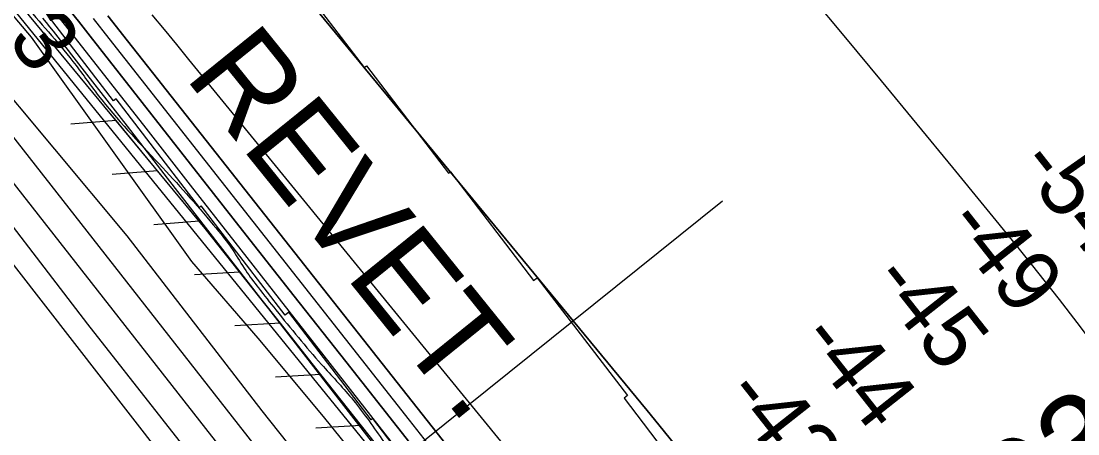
# Model space of a CAD drawing. Extents: x 3887375 to 3925618, y 296674 to 322633.
# Drawn here: x 3898902 to 3900036, y 305455 to 305898 of the extents above; entities that cross this region are included whole.
import ezdxf

# ---------------------------------------------------------------- set-up
doc = ezdxf.new("R2010")
doc.units = 0
for name, color, linetype in [('V-LEVE-TOET', 7, 'Continuous'), ('V-RIVR-EDGE', 7, 'Continuous'), ('V-RIVR-RANG', 7, 'Continuous'), ('V-ROAD-CNTR', 7, 'Continuous'), ('V-RRAP-FSHR', 7, 'Continuous'), ('V-RRAP-RVMT', 7, 'Continuous'), ('V-RRAP-RVMT-IDEN', 7, 'Continuous'), ('V-SURV-IDEN', 7, 'Continuous'), ('V-SURV-LINE', 7, 'Continuous'), ('V-TOPO-DPTH', 7, 'Continuous'), ('V-TOPO-MAJR', 7, 'Continuous'), ('V-TOPO-MINR', 7, 'Continuous'), ('V-TOPO-WATR', 7, 'Continuous')]:
    doc.layers.add(name, color=color, linetype=linetype)

msp = doc.modelspace()

# ---------------------------------------------------------------- linework, layer by layer
at = {"layer": 'V-LEVE-TOET'}
for points in [[(3899860.4, 304585.9), (3899743.5, 304733.3), (3899648.1, 304858.4), (3899528.5, 305011.4), (3899410.5, 305160.9), (3899292.7, 305313), (3899160.3, 305479.7), (3899015.4, 305667.7), (3898859.9, 305853.6), (3898740.5, 306001.2), (3898607.8, 306162.6), (3898481.9, 306307.6), (3898354.9, 306454.3)], [(3899779.4, 304538), (3899658.3, 304689.7), (3899546.1, 304835.5), (3899406.7, 305015.3), (3899300.1, 305156.6), (3899132.6, 305369.5), (3898973.3, 305572.8), (3898838, 305748.7), (3898685.6, 305942.1), (3898540.7, 306112.6), (3898424.5, 306234)]]:
    msp.add_lwpolyline(points, dxfattribs=at)
at = {"layer": 'V-RIVR-EDGE'}
msp.add_spline([(3894498, 310522.4), (3894530, 310496.1), (3894553.8, 310474.7), (3894579.9, 310451.3), (3894614.8, 310419.2), (3894633.2, 310400.7), (3894662.8, 310372.4), (3894685.1, 310353.4), (3894692.4, 310347.1), (3894709.8, 310328.1), (3894746.6, 310285.3), (3894785.8, 310252.2), (3894809.6, 310225.9), (3894830.4, 310205.4), (3894852.7, 310189.9), (3894866.7, 310171.8), (3894915.2, 310120.3), (3894950.1, 310083.7), (3894971.4, 310062.8), (3894999, 310039.4), (3895025.2, 310017), (3895052.8, 309992.7), (3895093, 309952.3), (3895110.9, 309932.8), (3895141.4, 309903.1), (3895188.9, 309855.9), (3895222.8, 309821.3), (3895255.8, 309784.3), (3895319.2, 309722.5), (3895350.7, 309688.4), (3895358.4, 309676.3), (3895364.7, 309669.4), (3895374.9, 309663.1), (3895389, 309650.4), (3895410.8, 309628.1), (3895448.5, 309583.3), (3895480.5, 309554.1), (3895503.8, 309527.8), (3895533.8, 309499.5), (3895577.4, 309454.8), (3895606.9, 309425.5), (3895653.5, 309378.8), (3895685.9, 309349.1), (3895719.8, 309314.5), (3895749.4, 309285.8), (3895790.6, 309242.5), (3895837.1, 309195.8), (3895863.7, 309164.1), (3895900, 309127.6), (3895944.1, 309081.4), (3895955.7, 309070.7), (3895974.6, 309054.6), (3896002.3, 309033.1), (3896032.8, 309003.9), (3896062.8, 308972.3), (3896082.7, 308950.4), (3896119.5, 308911.9), (3896139.3, 308892.5), (3896152, 308889.5), (3896163.1, 308883.7), (3896167.9, 308873.9), (3896170.3, 308862.3), (3896184.4, 308844.3), (3896211, 308816), (3896224.1, 308810.2), (3896236.7, 308802.4), (3896249.8, 308786.8), (3896255.6, 308776.6), (3896270.6, 308766.4), (3896280.3, 308753.2), (3896295.8, 308737.2), (3896375.3, 308661.2), (3896425.2, 308610.1), (3896464.4, 308570.6), (3896519.6, 308515.6), (3896548.7, 308483), (3896563.2, 308467.5), (3896597.6, 308430.9), (3896635.9, 308396.4), (3896666.4, 308365.7), (3896681.4, 308349.6), (3896712.4, 308320.4), (3896746.3, 308287.3), (3896777.4, 308260), (3896801.6, 308235.7), (3896820.5, 308215.3), (3896842.8, 308195.3), (3896851.5, 308181.2), (3896882.5, 308148.6), (3896918.8, 308116.4), (3896962.9, 308074.6), (3896997.8, 308033.2), (3897029.2, 307998.6), (3897042.3, 307985), (3897083.5, 307945.6), (3897107.2, 307918.3), (3897123.2, 307898.8), (3897130, 307898.8), (3897142.1, 307893), (3897146, 307882.3), (3897149.9, 307874), (3897162.9, 307860.4), (3897188.6, 307833.1), (3897229.3, 307788.8), (3897267.6, 307752.3), (3897300.5, 307715.8), (3897334.4, 307680.3), (3897361.5, 307651.1), (3897384.8, 307628.2), (3897411.4, 307599), (3897445.8, 307563.4), (3897494.3, 307516.7), (3897543.2, 307462.7), (3897584.8, 307418.4), (3897609, 307394), (3897646.8, 307355.6), (3897678.8, 307323.9), (3897715.1, 307290.3), (3897752, 307253.3), (3897767, 307236.3), (3897837.7, 307158.4), (3897886.6, 307104.4), (3897936, 307048.4), (3897965.5, 307015.3), (3898010.6, 306970.1), (3898027.5, 306949.1), (3898045, 306936), (3898063.9, 306914.1), (3898089, 306882.5), (3898117.1, 306854.7), (3898160.2, 306801.2), (3898195.6, 306763.7), (3898235.8, 306719.9), (3898261.5, 306693.6), (3898297.3, 306650.8), (3898332.7, 306612.3), (3898369.9, 306568), (3898397.5, 306534.9), (3898422.2, 306505.8), (3898462.9, 306455.1), (3898495.3, 306417.2), (3898522, 306382.2), (3898601.4, 306284.3), (3898652.2, 306228.4), (3898693.4, 306177.3), (3898729.7, 306130.6), (3898777.1, 306074.1), (3898825.5, 306014.3), (3898848.8, 305986), (3898904, 305917.4), (3898957.2, 305854.7), (3898984.4, 305818.2), (3899049.7, 305744.7), (3899107.8, 305679.4), (3899129.1, 305651.7), (3899142.7, 305630.3), (3899156.2, 305611.8), (3899175.1, 305588), (3899224, 305529.6), (3899256, 305493.6), (3899288.9, 305449.3), (3899312.6, 305415.2), (3899375.6, 305336.9), (3899410.9, 305296), (3899442.8, 305252.2), (3899470.4, 305211.9), (3899531.4, 305133.5), (3899579.3, 305071.2), (3899616.1, 305026), (3899647.1, 304986.1), (3899690.7, 304931.1), (3899729.4, 304876.6), (3899753.6, 304846.9), (3899770.6, 304821.6), (3899817.5, 304755.5), (3899845.6, 304713.2), (3899868.3, 304677.2), (3899889.6, 304650.4), (3899911.4, 304623.6), (3899955.4, 304569.1), (3899987.4, 304526.8), (3900012.6, 304494.2), (3900025.6, 304476.2), (3900037.2, 304456.8), (3900061.9, 304431.9), (3900070.7, 304424.1), (3900074.5, 304414.4), (3900075, 304404.2), (3900073, 304397.9), (3900071.5, 304388.7), (3900071.5, 304383.8), (3900075.9, 304379), (3900087.1, 304374.1), (3900096.3, 304367.7), (3900108.4, 304362.4), (3900117.1, 304353.6), (3900140.8, 304326.3), (3900165.5, 304299.1), (3900226.1, 304227.6), (3900277.9, 304164.3), (3900320, 304105.9), (3900352.4, 304062.6), (3900384.4, 304023.2), (3900411.5, 303988.2), (3900438.1, 303954.1), (3900462.8, 303926.8), (3900556.2, 303812.5), (3900597.9, 303762.9), (3900633.7, 303716.6), (3900652.6, 303691.3), (3900702, 303626.6), (3900774.6, 303530.8), (3900849.1, 303437.3), (3900903.4, 303371.2), (3900928.1, 303343.4), (3900948.9, 303317.6), (3901001.2, 303258.3), (3901038.9, 303216.9), (3901074.8, 303173.1), (3901092.2, 303147.3), (3901171.6, 303050.5), (3901205, 303008.6), (3901238.4, 302968.2), (3901274.7, 302927.8), (3901303.3, 302893.8), (3901344, 302847.5), (3901366.7, 302816.4), (3901404.5, 302770.2), (3901454.4, 302715.2), (3901507.2, 302659.2), (3901551.7, 302608.1), (3901584.7, 302570.6), (3901650, 302491.3), (3901681, 302443.6), (3901717.8, 302388.2), (3901785.5, 302298.2), (3901789.5, 302293.3)], degree=3, dxfattribs=at)
at = {"layer": 'V-RIVR-RANG'}
msp.add_line((3899217.4, 305354.7), (3899654.3, 305705.1), dxfattribs=at)
at = {"layer": 'V-ROAD-CNTR'}
msp.add_lwpolyline([(3900007.6, 304176.7), (3899734.1, 304548.6), (3899476.4, 304888), (3899114.9, 305351.7), (3898676.4, 305915.9)], dxfattribs=at)
at = {"layer": 'V-RRAP-FSHR'}
for p, q in [((3899003.5, 305791.3), (3898954.8, 305787.4)), ((3899048.1, 305737.4), (3898999.4, 305733.5)), ((3899092.7, 305683.4), (3899044, 305679.5)), ((3899136.3, 305628.7), (3899087.6, 305625.8)), ((3899179.8, 305573.8), (3899131, 305570.9)), ((3899223.2, 305518.9), (3899174.5, 305516)), ((3899266.6, 305464), (3899217.9, 305461.2))]:
    msp.add_line(p, q, dxfattribs=at)
for points in [[(3891468.4, 312810.1), (3891592.1, 312735.5), (3892299.9, 312230.2), (3893039.2, 311719.3), (3893631.6, 311277.1), (3894117.7, 310846), (3894636.9, 310371.6), (3895242, 309786.8), (3895348.8, 309658.3), (3895604.3, 309398.3), (3896430.2, 308555.1), (3897023.9, 307973.7), (3897641.6, 307335.1), (3898033.6, 306930.9), (3898562.2, 306317.9), (3899280.4, 305434.2), (3899629.7, 304981.5), (3900046.2, 304414.8), (3900422.7, 303959.4), (3901188.8, 303011.8), (3901775.8, 302279.8)], [(3900183.2, 304271.3), (3899817.1, 304740.6), (3899521, 305137), (3899332.3, 305381.1), (3899099.3, 305675.5), (3898876.1, 305945.2), (3898644, 306227.4), (3898359.5, 306569.4), (3897911.8, 307067.9), (3897531.6, 307466.8), (3897152.8, 307863.4), (3896930.6, 308096.1), (3896288.1, 308742.1), (3895667.7, 309363.7), (3895267, 309773.2), (3894693.6, 310343.5)], [(3899003.5, 305791.3), (3898991.5, 305805.7)], [(3899048.1, 305737.4), (3899003.5, 305791.3)], [(3899092.7, 305683.4), (3899048.1, 305737.4)], [(3899136.3, 305628.7), (3899099.3, 305675.5), (3899092.7, 305683.4)], [(3899179.8, 305573.8), (3899136.3, 305628.7)], [(3899223.2, 305518.9), (3899179.8, 305573.8)], [(3899266.6, 305464), (3899223.2, 305518.9)], [(3899310.1, 305409.1), (3899266.6, 305464)]]:
    msp.add_lwpolyline(points, dxfattribs=at)
at = {"layer": 'V-RRAP-RVMT'}
for p, q in [((3899179.6, 305965.8), (3899269.7, 305848.2)), ((3899000.7, 305812.5), (3898911.6, 305928.8)), ((3899269.7, 305848.2), (3899272.1, 305850)), ((3899272.1, 305850), (3899360.4, 305734.7)), ((3899003.6, 305814.7), (3899000.7, 305812.5)), ((3899092.9, 305698.1), (3899003.6, 305814.7)), ((3899360.4, 305734.7), (3899362.3, 305736.2)), ((3899362.3, 305736.2), (3899451.6, 305619.7)), ((3899095, 305699.7), (3899092.9, 305698.1)), ((3899184.9, 305582.4), (3899095, 305699.7)), ((3899451.6, 305619.7), (3899455.4, 305622.6)), ((3899455.4, 305622.6), (3899552.4, 305496.1)), ((3899188.8, 305585.5), (3899184.9, 305582.4)), ((3899277.2, 305470.2), (3899188.8, 305585.5)), ((3899552.4, 305496.1), (3899548.7, 305493.3)), ((3899548.7, 305493.3), (3899629.8, 305387.4)), ((3899279, 305471.5), (3899277.2, 305470.2)), ((3899360.7, 305364.9), (3899279, 305471.5))]:
    msp.add_line(p, q, dxfattribs=at)
at = {"layer": 'V-SURV-LINE'}
for points in [[(3898747.3, 305959.5), (3899463.3, 305045.4)], [(3899439.7, 305026.9), (3898723.6, 305941)]]:
    msp.add_lwpolyline(points, dxfattribs=at)
at = {"layer": 'V-TOPO-DPTH'}
for points in [[(3900043.8, 304859.9), (3899670, 305357.1), (3899658.2, 305372.7), (3899646.4, 305388.2), (3899634.5, 305403.7), (3899622.5, 305419.1), (3899610.4, 305434.4), (3899598.3, 305449.7), (3899586, 305464.9), (3899573.6, 305480), (3899142.7, 306002.4)], [(3900043.8, 304859.9), (3899670, 305357.1), (3899658.2, 305372.7), (3899646.4, 305388.2), (3899634.5, 305403.7), (3899622.5, 305419.1), (3899610.4, 305434.4), (3899598.3, 305449.7), (3899586, 305464.9), (3899573.6, 305480), (3899142.7, 306002.4)], [(3899969.2, 304647.9), (3899950.2, 304671.3), (3899940, 304683.8), (3899929.8, 304696.3), (3899919.5, 304708.7), (3899909.3, 304721.2), (3899490.2, 305229.6), (3899481.2, 305240.6), (3899472.3, 305251.6), (3899463.4, 305262.6), (3899454.6, 305273.7), (3899361, 305392), (3899305.5, 305462.3), (3899250.1, 305532.6), (3899194.7, 305603), (3899139.3, 305673.4), (3898975.8, 305881.9), (3898963.3, 305897.7), (3898950.8, 305913.4)], [(3899909.3, 304721.2), (3899490.2, 305229.6), (3899481.2, 305240.6), (3899472.3, 305251.6), (3899463.4, 305262.6), (3899454.6, 305273.7), (3899361, 305392), (3899305.5, 305462.3), (3899250.1, 305532.6), (3899194.7, 305603), (3899139.3, 305673.4), (3898975.8, 305881.9), (3898963.3, 305897.7), (3898950.8, 305913.4)], [(3898924.6, 305901.2), (3898928.4, 305896.5), (3898932.2, 305891.8), (3898935.9, 305887), (3898971.9, 305840.9), (3898993.6, 305813.1), (3899015.3, 305785.3), (3899036.9, 305757.4), (3899058.5, 305729.5), (3899407, 305279.8), (3899426.2, 305255.2), (3899445.6, 305230.6), (3899465.1, 305206.2), (3899484.7, 305181.9), (3899692, 304926.4), (3899909.3, 304721.2)], [(3898994.6, 305903.7), (3899015.8, 305876.9), (3899468.8, 305303.2), (3899473.2, 305297.6), (3899477.7, 305292), (3899482.1, 305286.5), (3899486.5, 305280.9), (3899491.1, 305275), (3899493.3, 305272.4), (3899495.4, 305269.7), (3899497.6, 305267.1), (3899499.7, 305264.4), (3899501.9, 305261.8), (3899504.1, 305259.2), (3899506.2, 305256.6), (3899508.4, 305253.9), (3899974, 304693.1), (3899985, 304679.7), (3899996.1, 304666.3), (3900007, 304652.8)], [(3900007, 304652.8), (3899996.1, 304666.3), (3899985, 304679.7), (3899974, 304693.1), (3899508.4, 305253.9), (3899506.2, 305256.6), (3899504.1, 305259.2), (3899501.9, 305261.8), (3899499.7, 305264.4), (3899497.6, 305267.1), (3899495.4, 305269.7), (3899493.3, 305272.4), (3899491.1, 305275), (3899486.5, 305280.9), (3899482.1, 305286.5), (3899477.7, 305292), (3899473.2, 305297.6), (3899468.8, 305303.2), (3899015.8, 305876.9), (3898994.6, 305903.7)], [(3899042, 305904.8), (3899055.1, 305888.8), (3899068.2, 305872.8), (3899081.2, 305856.8), (3899502.5, 305341.4), (3899518.9, 305321.3), (3899535.3, 305301.1), (3899551.7, 305280.8), (3899568.1, 305260.5), (3899779.4, 304997.9), (3899820.7, 304946.7), (3899862, 304895.5), (3899903.3, 304844.4), (3899944.7, 304793.3), (3899980.5, 304749.2), (3900004, 304720.1), (3900027.5, 304691.1), (3900051, 304662)], [(3899042, 305904.8), (3899055.1, 305888.8), (3899068.2, 305872.8), (3899081.2, 305856.8), (3899502.5, 305341.4), (3899518.9, 305321.3), (3899535.3, 305301.1), (3899551.7, 305280.8), (3899568.1, 305260.5), (3899779.4, 304997.9), (3899820.7, 304946.7), (3899862, 304895.5), (3899903.3, 304844.4), (3899944.7, 304793.3), (3899980.5, 304749.2), (3900004, 304720.1), (3900027.5, 304691.1), (3900051, 304662)]]:
    msp.add_lwpolyline(points, dxfattribs=at)
at = {"layer": 'V-TOPO-MAJR'}
msp.add_lwpolyline([(3899748, 305926.2), (3899786.4, 305880), (3899824.7, 305833.7), (3899862.9, 305787.3), (3899901.1, 305740.9), (3899968.6, 305658.5), (3899972.9, 305653.2), (3899977.2, 305647.8), (3899981.5, 305642.5), (3899985.8, 305637.1), (3900015.7, 305599.1), (3900034.7, 305574.5), (3900053.4, 305549.8)], dxfattribs=at)
at = {"layer": 'V-TOPO-MINR'}
for points in [[(3897864.8, 306984), (3898490.3, 306380.3), (3898912.3, 305880.8), (3899084.4, 305640), (3899155.8, 305557.7), (3899225.6, 305473.9), (3899294.2, 305389.1), (3899378.5, 305282.7), (3899404.1, 305250.4), (3899429.8, 305218.2), (3899455.5, 305186.1), (3899481.3, 305154), (3899540.8, 305080.2)], [(3899142.7, 306002.4), (3899573.6, 305480), (3899586, 305464.9), (3899598.3, 305449.7), (3899610.4, 305434.4), (3899622.5, 305419.1), (3899634.5, 305403.7), (3899646.4, 305388.2), (3899658.2, 305372.7), (3899670, 305357.1), (3900043.8, 304859.9)], [(3898950.8, 305913.4), (3898963.3, 305897.7), (3898975.8, 305881.9), (3899139.3, 305673.4), (3899194.7, 305603), (3899250.1, 305532.6), (3899305.5, 305462.3), (3899361, 305392), (3899454.6, 305273.7), (3899463.4, 305262.6), (3899472.3, 305251.6), (3899481.2, 305240.6), (3899490.2, 305229.6), (3899909.3, 304721.2), (3899919.5, 304708.7), (3899929.8, 304696.3), (3899940, 304683.8), (3899950.2, 304671.3), (3899969.2, 304647.9)], [(3898939.6, 305905), (3898947.7, 305894.7), (3898955.8, 305884.5), (3899035.3, 305782.9), (3899083, 305721.9), (3899130.8, 305660.8), (3899178.7, 305599.8), (3899226.5, 305538.8), (3899432, 305276.5), (3899445.8, 305259.1), (3899459.6, 305241.6), (3899473.6, 305224.3), (3899487.6, 305207.1), (3899843.3, 304772.6)], [(3898994.6, 305903.7), (3899015.8, 305876.9), (3899468.8, 305303.2), (3899473.2, 305297.6), (3899477.7, 305292), (3899482.1, 305286.5), (3899486.5, 305280.9), (3899491.1, 305275), (3899493.3, 305272.4), (3899495.4, 305269.7), (3899497.6, 305267.1), (3899499.7, 305264.4), (3899501.9, 305261.8), (3899504.1, 305259.2), (3899506.2, 305256.6), (3899508.4, 305253.9), (3899974, 304693.1), (3899985, 304679.7), (3899996.1, 304666.3), (3900007, 304652.8)], [(3899042, 305904.8), (3899055.1, 305888.8), (3899068.2, 305872.8), (3899081.2, 305856.8), (3899502.5, 305341.4), (3899518.9, 305321.3), (3899535.3, 305301.1), (3899551.7, 305280.8), (3899568.1, 305260.5), (3899779.4, 304997.9), (3899820.7, 304946.7), (3899862, 304895.5), (3899903.3, 304844.4), (3899944.7, 304793.3), (3899980.5, 304749.2), (3900004, 304720.1), (3900027.5, 304691.1), (3900051, 304662)], [(3898978.9, 305900.7), (3898995.7, 305879.4), (3899318, 305469.8), (3899345.5, 305434.8), (3899373.1, 305399.9), (3899400.7, 305365), (3899428.3, 305330.2), (3899475, 305271.3), (3899479.3, 305265.9), (3899483.6, 305260.5), (3899488, 305255.1), (3899492.4, 305249.8), (3899593.7, 305126.9), (3899648.8, 305060.2), (3899703.9, 304993.4), (3899758.9, 304926.6), (3899814, 304859.8), (3899971.4, 304668.6), (3899976.8, 304662), (3899982.2, 304655.4), (3899987.6, 304648.8)]]:
    msp.add_lwpolyline(points, dxfattribs=at)
at = {"layer": 'V-TOPO-WATR'}
msp.add_lwpolyline([(3898924.6, 305901.2), (3898928.4, 305896.5), (3898932.2, 305891.8), (3898935.9, 305887), (3898971.9, 305840.9), (3898993.6, 305813.1), (3899015.3, 305785.3), (3899036.9, 305757.4), (3899058.5, 305729.5), (3899407, 305279.8), (3899426.2, 305255.2), (3899445.6, 305230.6), (3899465.1, 305206.2), (3899484.7, 305181.9), (3899692, 304926.4)], dxfattribs=at)

# ---------------------------------------------------------------- texts
at = {"layer": 'V-RIVR-RANG'}
for s, rotation, p in [('4.3', 306.9883, (3898840.7, 305937.4)), ('-54', 308.2654, (3899969.2, 305743.3)), ('-49', 308.2654, (3899891.8, 305679.9)), ('-45', 308.2654, (3899812, 305619.7)), ('-44', 308.2654, (3899734.5, 305556.5)), ('-42', 308.2654, (3899654, 305497))]:
    msp.add_text(s, height=67, rotation=rotation, dxfattribs=at).set_placement(p)
at = {"layer": 'V-RRAP-RVMT-IDEN'}
msp.add_text('REVET.', height=100, rotation=308.905, dxfattribs=at).set_placement((3899075.9, 305838.5))
at = {"layer": 'V-SURV-IDEN'}
msp.add_text('1545+93.2', height=100, rotation=37.0894, dxfattribs=at).set_placement((3899681.7, 305115.3))

doc.saveas('drawing.dxf')
